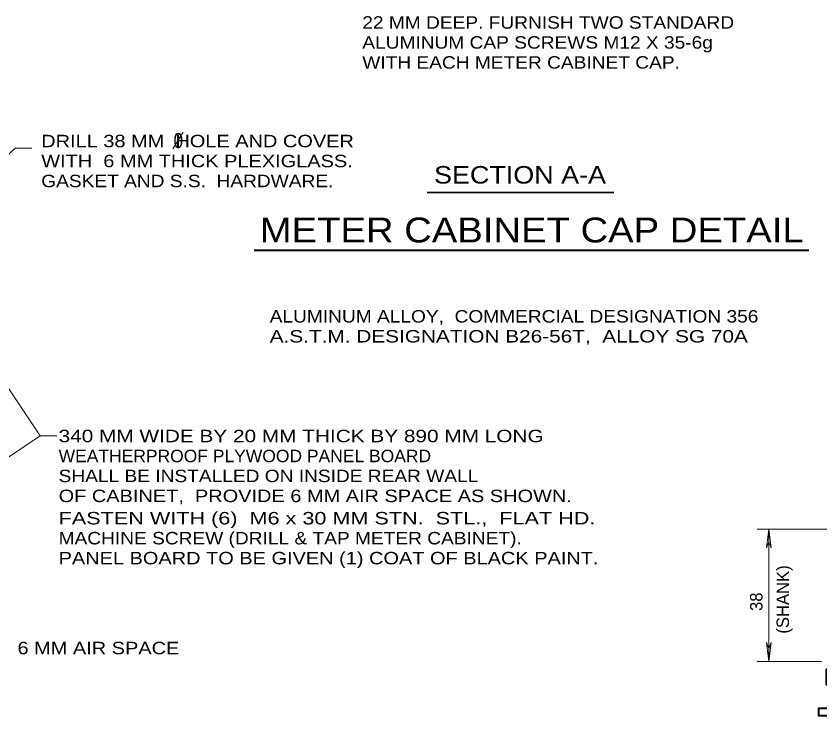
# Model space of a CAD drawing. Extents: x 312583 to 312853, y 144419 to 144586.
# Drawn here: x 312716.69 to 312765.82, y 144489.24 to 144532.01 of the extents above; entities that cross this region are included whole.
import ezdxf
from ezdxf.enums import TextEntityAlignment as Align

# ---------------------------------------------------------------- set-up
doc = ezdxf.new("R2010")
doc.units = 0
doc.header["$LTSCALE"] = 0.3
doc.layers.add('1', color=7, linetype='Continuous', lineweight=40)
doc.layers.add('2', color=7, linetype='Continuous', lineweight=13)

msp = doc.modelspace()

# ---------------------------------------------------------------- linework, layer by layer
at = {"layer": '1'}
msp.add_lwpolyline([(312768.1377, 144489.2426), (312765.761, 144489.2426), (312765.761, 144489.7179), (312766.7117, 144489.7179), (312766.7117, 144490.1933), (312767.187, 144490.1933), (312767.187, 144490.6686), (312767.6624, 144490.6686), (312767.6624, 144491.1439), (312766.2364, 144491.1439), (312766.2364, 144491.6193), (312766.2364, 144492.0946), (312766.7117, 144492.0946), (312766.7117, 144492.5699), (312768.1377, 144492.5699)], dxfattribs=at)
at = {"layer": '2'}
for p, q in [((312726.2654, 144523.8945), (312726.9017, 144524.9218)), ((312718.1501, 144506.3521), (312719.1698, 144506.3521)), ((312766.6427, 144500.6659), (312761.9814, 144500.6659)), ((312762.702, 144500.6659), (312762.5564, 144499.5083)), ((312762.702, 144492.5699), (312762.702, 144500.6659)), ((312762.702, 144500.6659), (312762.8477, 144499.5083)), ((312762.5564, 144499.5083), (312762.702, 144499.8763)), ((312762.8477, 144499.5083), (312762.702, 144499.8763)), ((312762.5564, 144493.7276), (312762.702, 144493.3596)), ((312762.702, 144492.5699), (312762.5564, 144493.7276)), ((312762.8477, 144493.7276), (312762.702, 144493.3596)), ((312762.702, 144492.5699), (312762.8477, 144493.7276)), ((312765.922, 144492.5699), (312761.9814, 144492.5699))]:
    msp.add_line(p, q, dxfattribs=at)
at = {"layer": '2', "lineweight": 35}
msp.add_line((312741.8168, 144521.2356), (312753.2266, 144521.2356), dxfattribs=at)
at = {"layer": '2', "lineweight": 40}
msp.add_line((312731.2342, 144517.7041), (312765.1446, 144517.7041), dxfattribs=at)
at = {"layer": '2'}
for points in [[(312711.67, 144519.3843), (312716.6329, 144523.9334), (312717.6526, 144523.9334)], [(312713.4563, 144503.2076), (312718.1501, 144506.3521), (312713.2646, 144513.6803)]]:
    msp.add_lwpolyline(points, dxfattribs=at)

# ---------------------------------------------------------------- texts
for s, width, p in [('22 MM DEEP. FURNISH TWO STANDARD ', 1.15, (312737.8499, 144531.2426)), ('ALUMINUM CAP SCREWS M12 X 35-6g', 1.15, (312737.8499, 144530.0226)), ('WITH EACH METER CABINET CAP.', 1.15, (312737.8499, 144528.8026)), ('DRILL 38 MM  HOLE AND COVER', 1.2, (312718.225, 144523.997)), ('WITH  6 MM THICK PLEXIGLASS.', 1.2, (312718.225, 144522.777)), ('GASKET AND S.S.  HARDWARE.', 1.15, (312718.225, 144521.557)), ('ALUMINUM ALLOY,  COMMERCIAL DESIGNATION 356', 1.15, (312732.1905, 144513.2844)), ('A.S.T.M. DESIGNATION B26-56T,  ALLOY SG 70A', 1.25, (312732.1905, 144512.0644)), ('340 MM WIDE BY 20 MM THICK BY 890 MM LONG', 1.25, (312719.2867, 144505.9702)), ('WEATHERPROOF PLYWOOD PANEL BOARD', 1.05, (312719.2867, 144504.7502)), ('SHALL BE INSTALLED ON INSIDE REAR WALL', 1.15, (312719.2867, 144503.5302)), ('OF CABINET,  PROVIDE 6 MM AIR SPACE AS SHOWN.', 1.2, (312719.2867, 144502.3102)), ('FASTEN WITH (6)  M6 x 30 MM STN.  STL.,  FLAT HD.', 1.3, (312719.2868, 144500.9467)), ('MACHINE SCREW (DRILL & TAP METER CABINET).', 1.15, (312719.2868, 144499.7267)), ('PANEL BOARD TO BE GIVEN (1) COAT OF BLACK PAINT.', 1.2, (312719.2868, 144498.5067)), ('6 MM AIR SPACE', 1.2, (312716.7721, 144493.0119))]:
    msp.add_text(s, height=0.76, dxfattribs=dict(at, width=width)).set_placement(p)
for s, height, width, p in [('0', 0.92, 0.85, (312726.6027, 144523.9481)), ('SECTION A-A', 1.07, 1.15, (312747.4927, 144521.7777)), ('METER CABINET CAP DETAIL', 1.52, 1.15, (312748.2062, 144518.1796))]:
    msp.add_text(s, height=height, dxfattribs=dict(at, width=width)).set_placement(p, align=Align.CENTER)
for s, p in [('(SHANK)', (312763.9337, 144494.2703)), ('38', (312762.3141, 144495.6562))]:
    msp.add_text(s, height=0.76, rotation=90, dxfattribs=at).set_placement(p)

doc.saveas('drawing.dxf')
